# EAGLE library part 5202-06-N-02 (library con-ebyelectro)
Barrier Blocks Sreies 5202 Source: http://www.ebyelectro.com/PDF/5202-XX-N-02.pdf
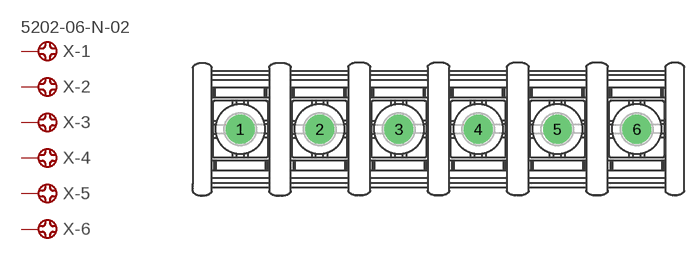
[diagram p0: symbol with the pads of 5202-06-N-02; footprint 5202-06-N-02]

Designator prefix X; gates -1=CONNECT-VALUE -2=CONNECT -3=CONNECT -4=CONNECT -5=CONNECT -6=CONNECT

## 5202-06-N-02 (OC_FARNELL: unknown; OC_NEWARK: unknown)  [5202-06-N-02]
1  -1:1  pas
2  -2:1  pas
3  -3:1  pas
4  -4:1  pas
5  -5:1  pas
6  -6:1  pas

## Footprint 5202-06-N-02 (pad centres in mm)
Barrier Blocks Sreies 5202 Source: http://www.ebyelectro.com/PDF/5202-XX-N-02.pdf
drill 1.5 pad 3 round: 1 -20.625,0; 2 -12.375,0; 3 -4.125,0; 4 4.125,0; 5 12.375,0; 6 20.625,0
